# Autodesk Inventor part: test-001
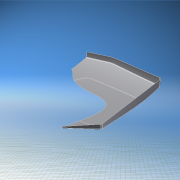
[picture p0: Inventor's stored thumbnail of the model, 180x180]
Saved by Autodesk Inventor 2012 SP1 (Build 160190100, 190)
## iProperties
Created: 2012-02
Part Number: test-001
Material: Default
Document SubType Name: Modeling
Designer: hg
Density: 1 g/cm^3
Mass: 28.7829 g
Surface Area: 5744.93 cm^2
Volume: 28.7829 cm^3
Übersetzungsnorm: STEP AP214IS
Dateiname: X:\AAA\Temp\120210_Proj_CL_Schneidwerk_C4\test-rechts.stp
Vorprozessor: Autodesk Inventor 2012
Postprozessor: Build: 190, Release: 2012 SP1 - Date: Mon 08/08/2011
Gesendete Einheiten: Millimeter
Unbestimmtheit: 0.01
Author: hg
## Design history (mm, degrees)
feature "Zusammengesetzt3"
feature "Verdickung1" dims "d6" = 0.1, "d7" = 0.1
node "Volumenkörper1"
node "Flächen6"
